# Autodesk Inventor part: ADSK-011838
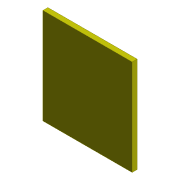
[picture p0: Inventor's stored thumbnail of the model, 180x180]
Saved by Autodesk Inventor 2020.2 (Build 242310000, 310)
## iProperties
Created: 1999-11
Part Number: ADSK-011838
Document SubType Name: Modeling
Designer: sspink
Material: Générique
Density: 1 g/cm^3
Appearance: Gelb
Mass: 9.396 g
Surface Area: 69.36 cm^2
Volume: 9.396 cm^3
Control State: 0
Checked Out: False
Last Check In By: sspink
Last Check In Date: 1999-12-22
Master: False
Shininess: 0.0
Length Units: 11269
Angle Units: 11279
Time Units: 11290
Mass Units: 11283
Length Display Precision: 3
Angle Display Precision: 2
Compacted: True
Dimensions: 58x3x54 mm
Mass: 0,009 kg
VLT_Material: Generisch
Density: 0.0
Volumn: 0.0
Area: 0.0
PropertySet Name: Model Information
Author: sspink
Revision Number: -
Title: ADSK-011838
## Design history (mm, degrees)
node "Solide1"
  node "Extrusion1" dims "d2" = 3, "d3" = 0
sketch "Sketch1"
  geometry: L1 (-222.936, 35.799)-(-168.936, 35.799); L2 (-168.936, 35.799)-(-168.936, 93.799); L3 (-168.936, 93.799)-(-222.936, 93.799) reference; L4 (-222.936, 93.799)-(-222.936, 35.799) reference
  constraints: 8 end point, 2 horizontal, 2 parallel, 1 perpendicular, 1 vertical
  dimensions: "d0" = 58 distance of L1.end L2.end; "d1" = 54 distance of L1.start L1.end
node "Corps solides"
node "Corps surfaciques"
